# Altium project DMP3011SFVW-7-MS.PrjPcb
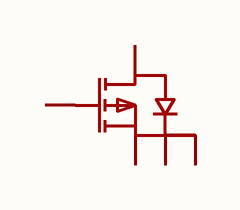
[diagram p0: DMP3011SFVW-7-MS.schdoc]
1 sheet, 1 parts. Net scope: global (net labels, ports and power ports of the same name join across sheets).

## Sheet DMP3011SFVW-7-MS.schdoc
size 127 x 101 mm

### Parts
Q?  dmp3011sfvw-7-ms  [PDFN3333-8_L3.1-W3.2-P0.65-LS3.4-BL_1]  (value not drawn)

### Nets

Not connected (* = marked no-connect by the designer): Q? 1(S) 2(S) 3(S) 4(G) 5(D)

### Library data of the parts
Q? = dmp3011sfvw-7-ms: 数量:1个P沟道;漏源电压(Vdss):30V;连续漏极电流(Id):-;导通电阻(RDS(on)):8.5mΩ@10V;耗散功率(Pd):21.5W;阈值电压(Vgs(th)):1.5V;; Manufacturer: MSKSEMI(美森科); AddInBom: yes; ModelId: c288237aeb774e1d92142cc9eea176d4; ModelTransform: 118.8974,118.8974,0,90,0,0,0,19.486,0; Number: 1个P沟道; Drain to Source Voltage: 30V; Pd - Power Dissipation: 21.5W; Gate Threshold Voltage (Vgs(th)): 1.5V; Gate Charge(Qg): 30nC; Input Capacitance(Ciss): 2.8nF; Reverse Transfer Capacitance (Crss@Vds): 319pF; Type: P沟道; Output Capacitance(Coss): 346pF; Vgs: ±20V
